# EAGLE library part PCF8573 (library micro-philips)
I2C-Bus CLOCK/CALENDAR with power fail detector
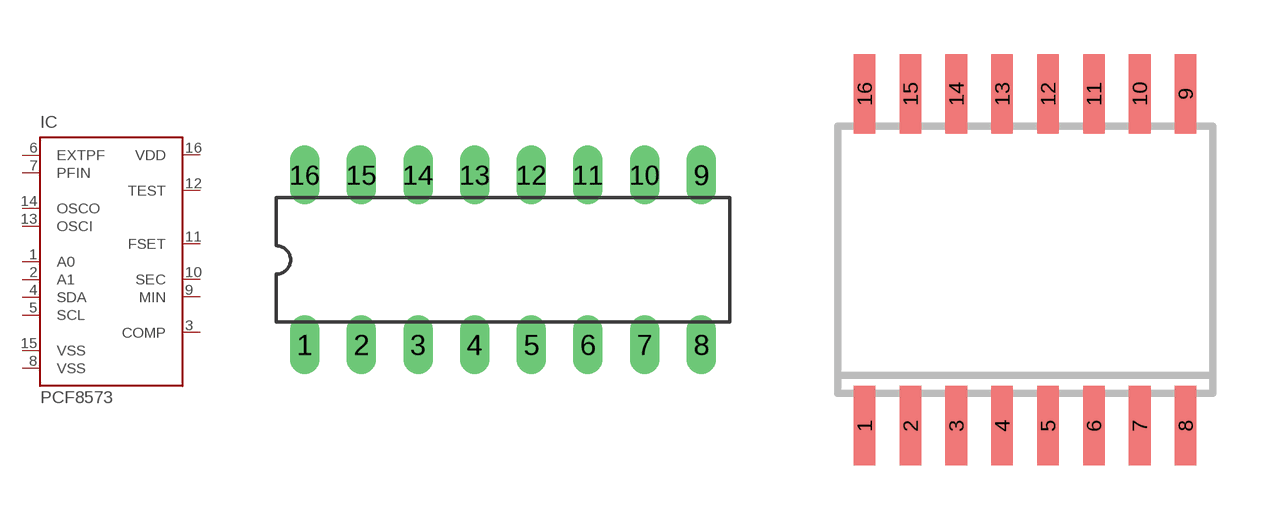
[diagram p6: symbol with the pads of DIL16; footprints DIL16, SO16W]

Designator prefix IC

## PCF8573P (OC_FARNELL: unknown; OC_NEWARK: unknown)  [DIL16]
1  A0  in
2  A1  in
3  COMP  out
4  SDA
5  SCL  in
6  EXTPF  in
7  PFIN  in
8  VSS  pwr
9  MIN  out
10  SEC  out
11  FSET  out
12  TEST  in
13  OSCI  in
14  OSCO  out
15  VSS  pwr
16  VDD  pwr

## PCF8573T (OC_FARNELL: unknown; OC_NEWARK: unknown)  [SO16W]
Pads as for DIL16

## Footprint DIL16 (pad centres in mm)
Dual In Line
drill 0.813 long: 1 -8.89,-3.81; 2 -6.35,-3.81; 3 -3.81,-3.81; 4 -1.27,-3.81; 5 1.27,-3.81; 6 3.81,-3.81; 7 6.35,-3.81; 8 8.89,-3.81; 9 8.89,3.81; 10 6.35,3.81; 11 3.81,3.81; 12 1.27,3.81; 13 -1.27,3.81; 14 -3.81,3.81; 15 -6.35,3.81; 16 -8.89,3.81

## Footprint SO16W (pad centres in mm)
Small Outline Package 7.6 x 10.6 mm
smd 0.6 x 2.2: 1 -4.445,-4.6; 2 -3.175,-4.6; 3 -1.905,-4.6; 4 -0.635,-4.6; 5 0.635,-4.6; 6 1.905,-4.6; 7 3.175,-4.6; 8 4.445,-4.6; 9 4.445,4.6; 10 3.175,4.6; 11 1.905,4.6; 12 0.635,4.6; 13 -0.635,4.6; 14 -1.905,4.6; 15 -3.175,4.6; 16 -4.445,4.6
